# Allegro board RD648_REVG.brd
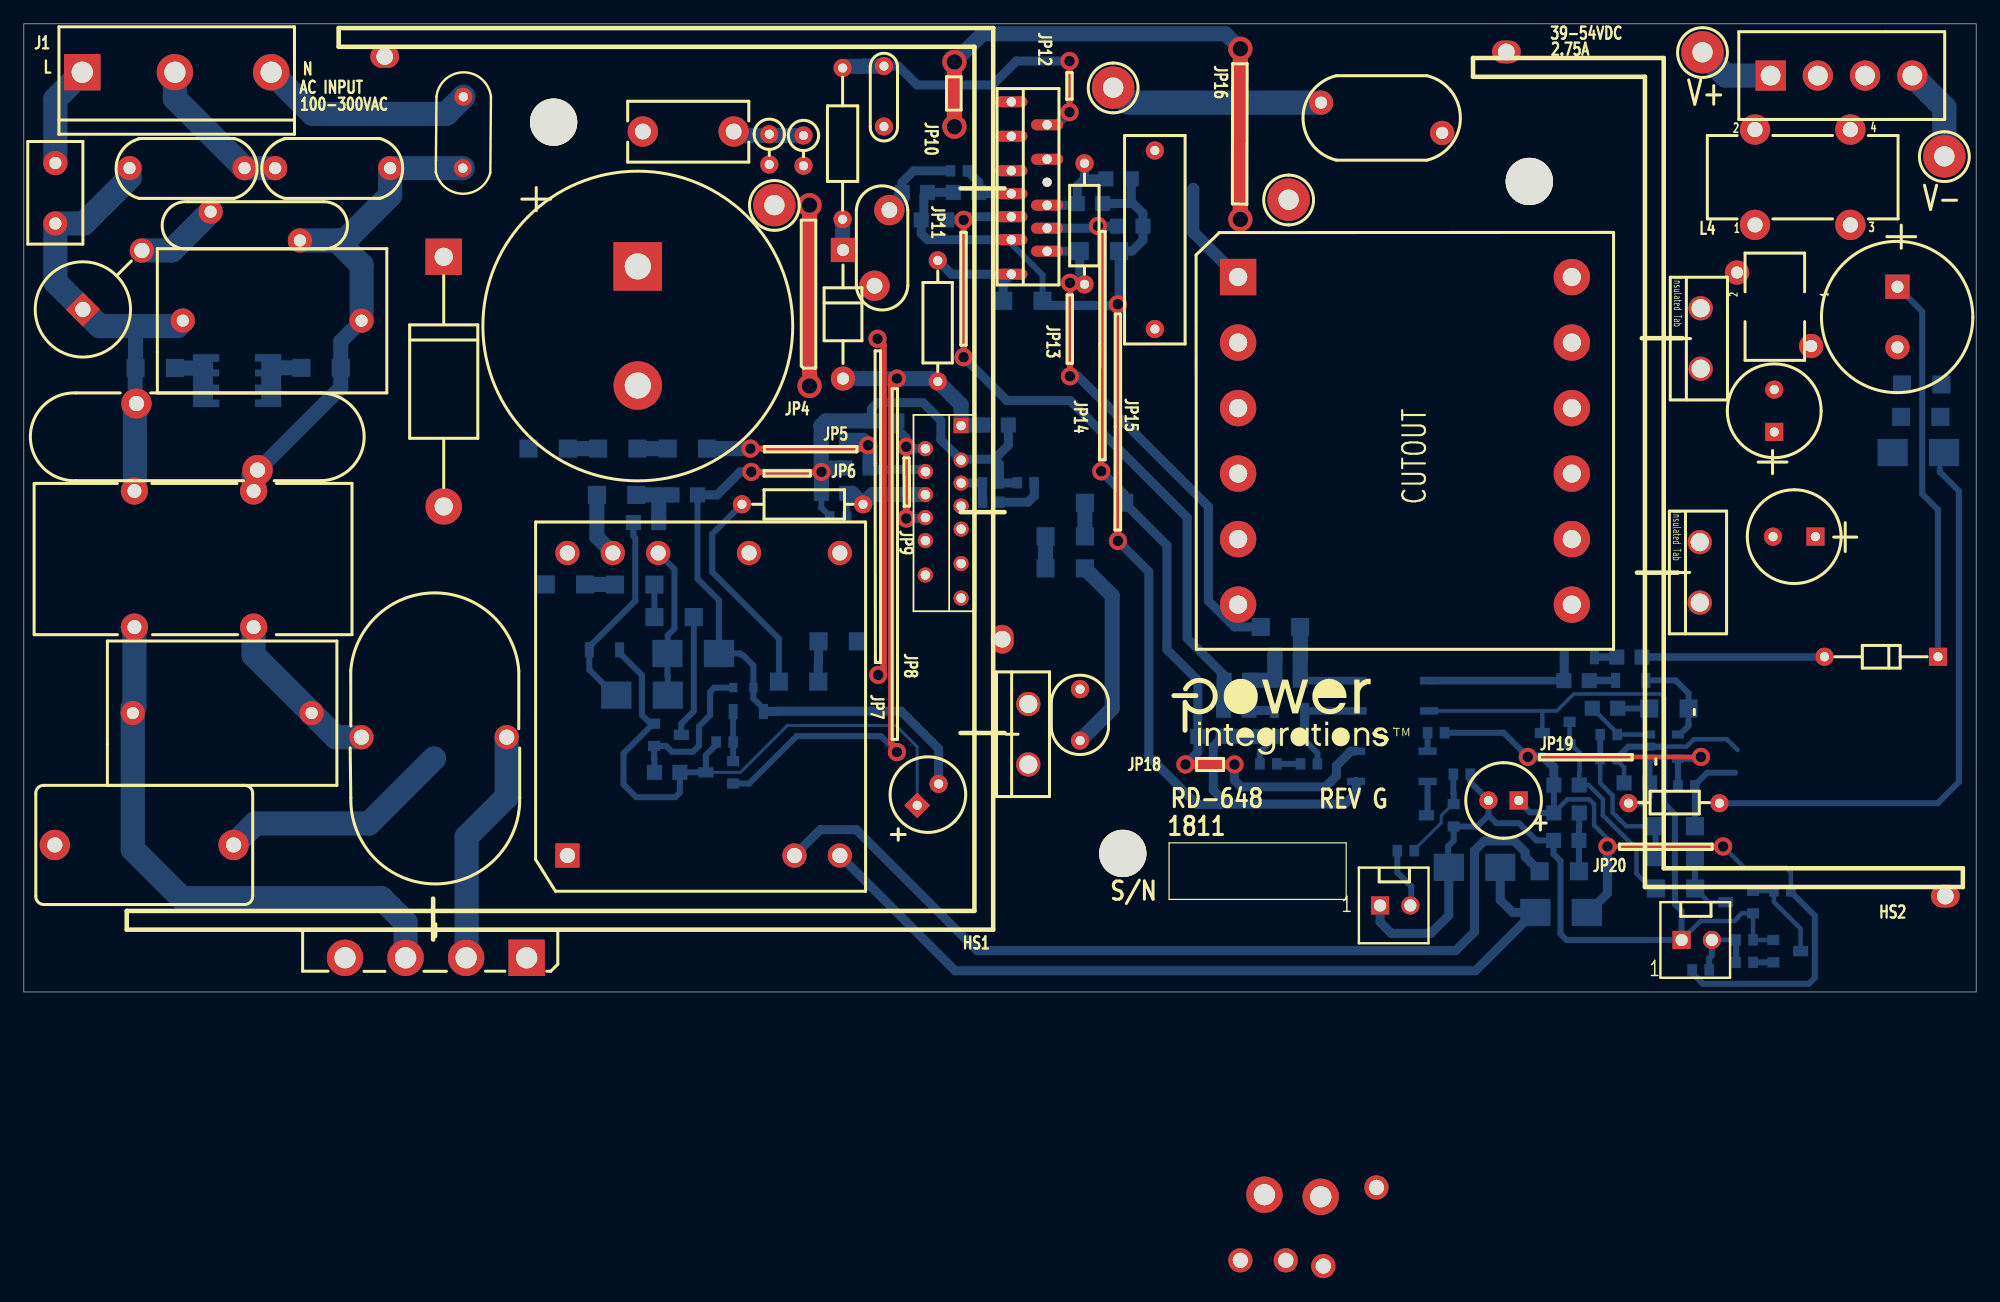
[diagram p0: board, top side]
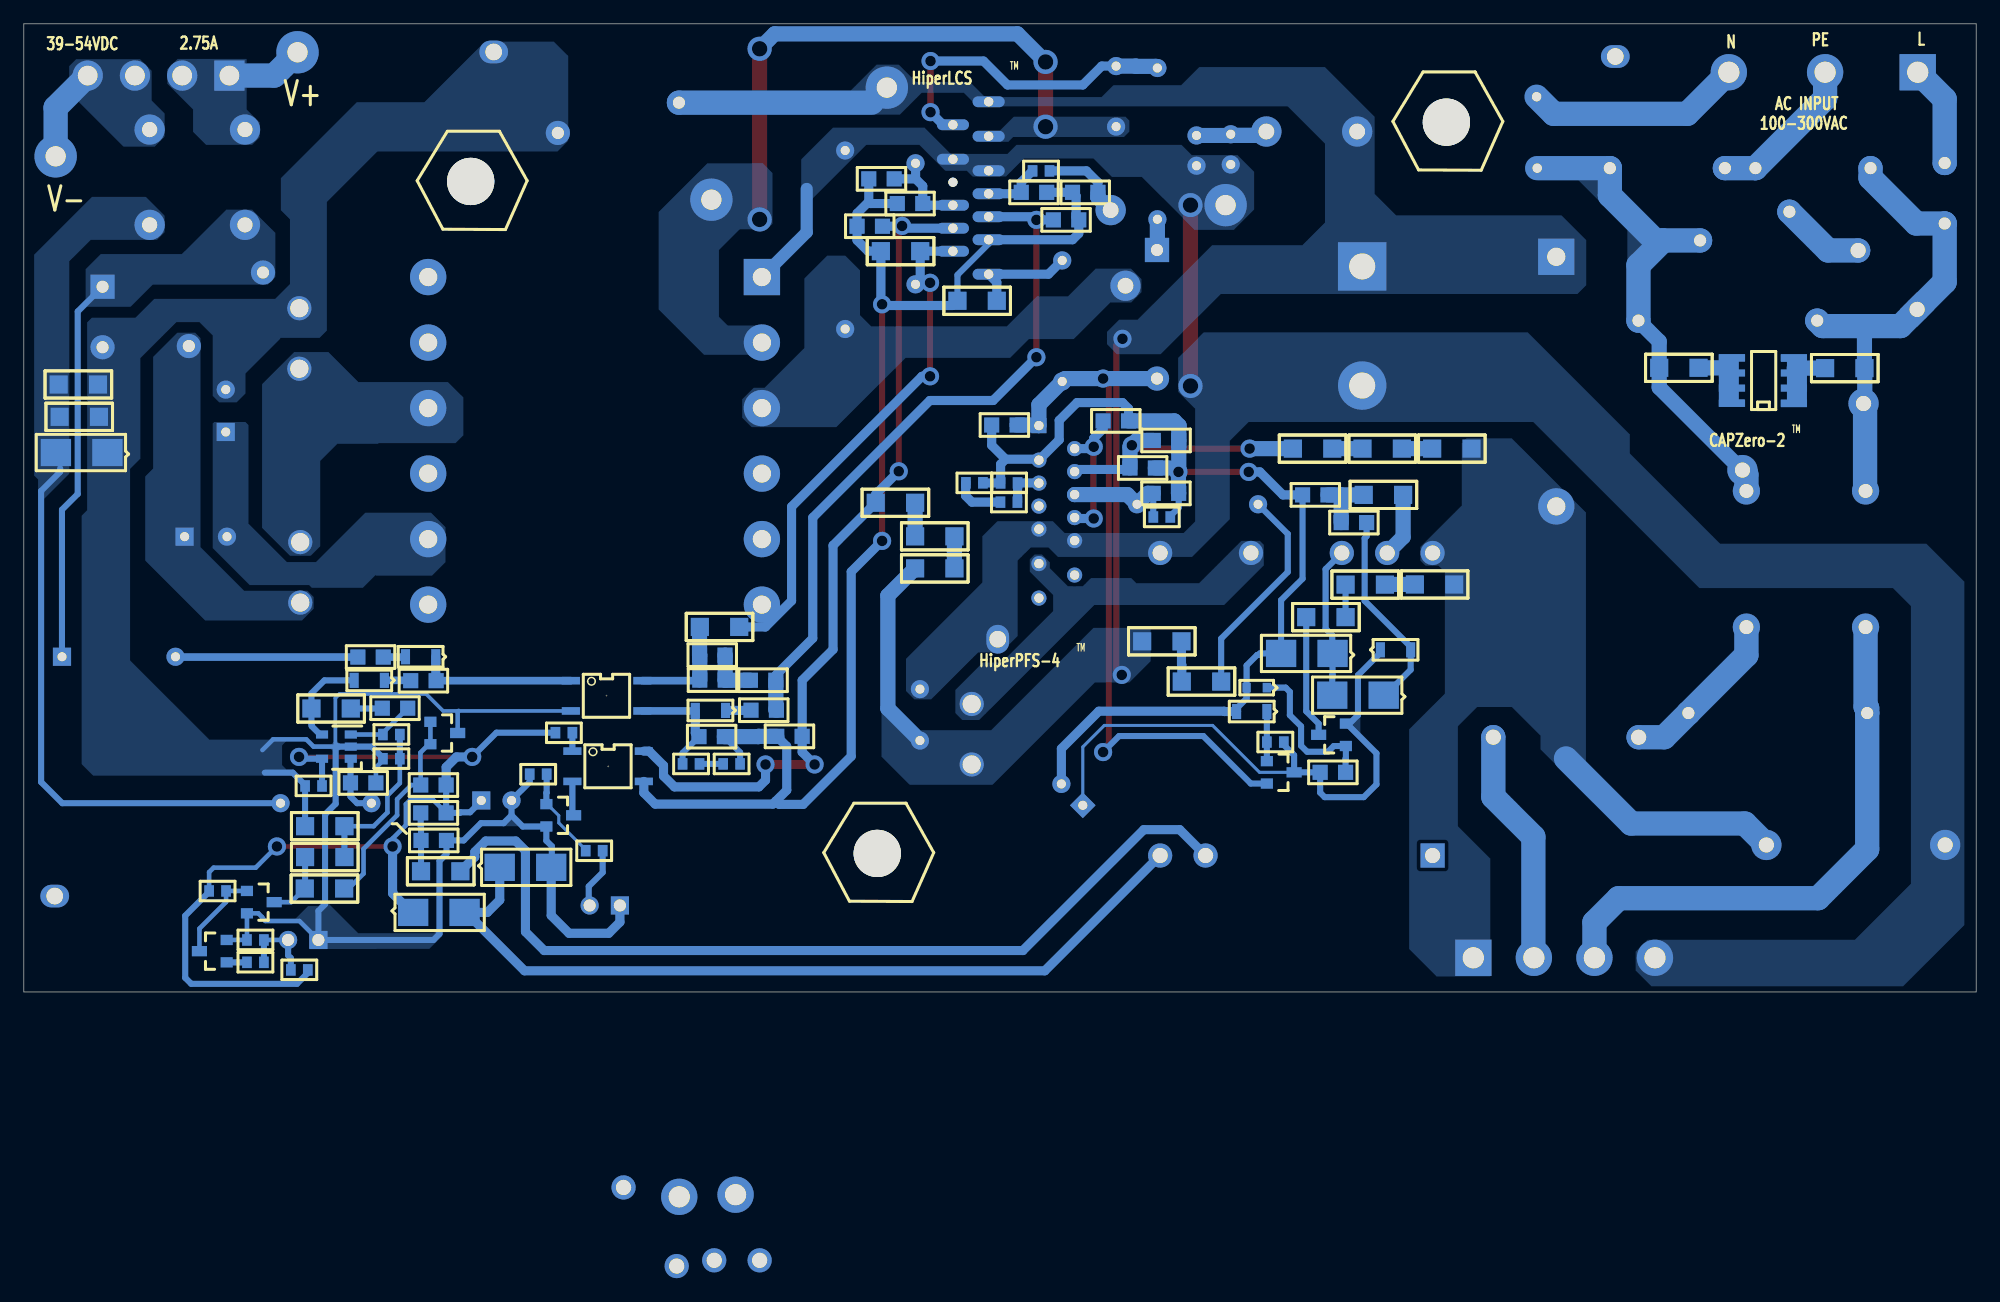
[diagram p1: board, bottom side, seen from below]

Outline 163.8 x 81.28 mm; copper layers: TOP, BOTTOM. Coordinates in mm from the lower left corner of the outline.
Outline path: 0,81.28 163.8,81.28 163.8,0 0,0 0,81.28

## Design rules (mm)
constraint set DEFAULT: min track width 0.508

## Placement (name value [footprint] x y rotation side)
BR1  GBU8J  [PIDAXBRIDGEGBU8]  42.19 2.87 180 top
C1  680 pF  [PINPYCAPRAD470X210LS380040]  8.86 69.16 0 top
C2  680 pF  [PINPYCAPRAD470X210LS380040]  21.08 69.16 0 top
C3  680 nF  [PINPXCAPRAD710X430720040]  13.34 56.36 0 top
C4  680 nF  [PINPXCAPRAD710X430720040]  9.14 23.42 0 top
C5  0.68 uF  [PI_NP_CAPRAD18P2X10LS15MMD050]  17.6 12.34 180 top
C6  100 nF  [PISMC0805]  51.14 39.41 0 bottom
C7  100 nF  [PISMC0805]  54.38 41.73 0 bottom
C8  100 nF  [PISMC0805]  128.37 15.04 0 bottom
C9  100 nF  [PISMC0805]  130.48 12.73 180 bottom
C10  220 uF  [PIPOLCAPCYLD250LS100030]  125.43 16.08 180 top
C11  100 uF  [PIPOLCAPCYLD250LS100030]  74.96 15.67 45 top
C12  3.3 uF  [PISMC0805]  80.47 47.6 0 bottom
C13  1 uF  [PISMC0805]  73.25 47.94 180 bottom
C14  470 pF  [PISMC0805]  71 43.99 180 bottom
C15  100 nF  [PISMC0603]  80.43 42.74 0 bottom
C16  1 uF  [PISMC0603]  84.76 42.75 180 bottom
C17  10 nF  [PI_NP_CAP250X200LS170D030]  88.62 21.11 90 top
C18  470 pF  [PISMC0805]  69.04 41.86 180 bottom
C19  100 uF  [PIPOLCAPCLYD25MMLS10MMD086]  51.51 60.91 270 top
C20  2.2 nF  [PINPYCAPRAD540X290LS400040]  108.84 74.66 0 top
C21  680 nF  [PISMC0805]  107.09 26.19 180 bottom
C22  22 nF  [PISMC0805]  91.76 64.29 0 bottom
C23  4.7 nF  [PISMC0805]  88.38 66.19 0 bottom
C24  1 uF  [PISMC1206]  88.6 62.19 0 bottom
C25  1 uF  [PISMC1206]  82.17 58.03 0 bottom
C26  4.7 nF  [PISMC0805]  77.43 64.82 180 bottom
C27  1 nF  [PISMC0805]  80.12 67.13 180 bottom
C28  47 nF  [PI_NP395X200LS300D040]  51.94 72.24 0 top
C29  12nF  [PI_NP_CAP689X200LS590D030]  94.89 70.65 270 top
C30  47 pF  [PINPCAPRAD370X156250040]  72.64 65.64 270 top
C31  330 nF  [PINPCAPRAD200X100200030]  72.16 77.73 270 top
C32  82 uF  [PIPOLCAPCLYD320LS140030]  150.32 38.23 180 top
C33  82 uF  [PIPOLCAPCLYD320LS140030]  146.86 47.02 90 top
C34  180 uF  [PIPOLCAPCLYD500LS200040]  157.2 59.21 270 top
C35  6.8 nF  [PISMC0805]  131.6 23.83 0 bottom
C36  100 nF  [PISMC0603]  138.79 17.3 0 bottom
C37  1 uF  [PISMC1206]  136.91 13.92 0 bottom
C38  3.3 nF  [PISMC0805]  136.4 17.55 180 bottom
C39  100 nF  [PISMC0603]  105.13 19.15 180 bottom
D1  BAV19WS  [PISMSOD323]  49.99 28.73 180 bottom
D2  ES1C-13-F  [PISMDO214AC12]  49.71 24.92 0 bottom
D3  ES1C-13-F  [PISMDO214AC12]  54 28.42 0 bottom
D4  1N5407-E3/54  [PIDV300X200X060DO15D0201AD]  35.23 61.72 270 top
D5  ES1C-13-F  [PISMDO214AC12]  131.14 6.68 180 bottom
D6  ES1C-13-F  [PISMDO214AC12]  123.88 10.46 180 bottom
D7  LXA03T600  [PIDVT0220ACREVA]  84.28 24.18 270 top
D8  BAV19WS  [PISMSOD323]  104.93 23.64 0 bottom
D9  UF4005  [PIDAX475X125040DO41]  68.73 62.29 270 top
D10  MBRF10H100-E3/45  [PIDVITO220FPAC]  140.61 37.77 270 top
D11  MBRF10H100-E3/45  [PIDVITO220FPAC]  140.69 57.4 270 top
D12  BAV19WS  [PISMSOD323]  129.24 28.14 0 bottom
D13  BAV19WS  [PISMSOD323]  133.55 26.16 0 bottom
D14  GS1A-LTP  [PISMDO214AC12]  156.79 45.29 0 bottom
F1  3.15 A  [PI_RST_MICROFUSE]  2.64 69.6 270 top
GDT1  GDT 500V  [PI_AXD8XL6MM050V]  4.95 57.3 45 top
HS1  HEATSINK,  FAB, DER648, PI CUST  [HS_2P_DER648A]  81.33 5.23 0 top
HS2  HEATSINK,  FAB, DER648, PI CUST  [HS_2P_DER648B]  136.02 8.81 270 top
J1  CON5  [PI_HDR_5PIN_LS156_LCK]  4.9 77.22 90 top
J2  CON2  [PI_MOLEX_2POL]  139.09 4.37 0 top
J3  CON4  [PI_HDR_4PIN]  146.56 76.93 270 top
J6  CON2  [PI_MOLEX_2POL]  113.79 7.26 0 top
JP1  0.0  [PISMR1206]  48.08 41.73 0 bottom
JP2  0.0  [PISMR1206]  127.18 10.13 0 bottom
JP3  0.0  [PISMR1206]  103.78 30.65 0 bottom
L1  9 mH  [PI_IND_4P_500X1050LS450D46]  19.28 42.06 270 top
L2  330 uH  [PI_TOROID_2P_550X950_LS480_D050]  28.32 21.39 0 top
L3  300 nH  [PI_OUT_DER648]  146.91 57.53 90 top
L4  120 uH  [PI_TOROID_DER648CMC]  149.25 68.4 0 top
NOREF  -  []  -0.03 81.28 0 top
NOREF#2  -  []  -228.45 -139.73 0 top
NOREF#3  -  []  96.29 26.34 0 top
NOREF#4  -  []  0 0 90 top
NOREF#5  -  []  -95.48 52.65 0 top
POST-CRKT_BRD_6-32_HEX1  Post Hex, 6-32, snap, 0.50"L, NYL  [PIMTGHOLED156]  44.45 73.03 180 bottom
POST-CRKT_BRD_6-32_HEX2  Post Hex, 6-32, snap, 0.50"L, NYL  [PIMTGHOLED156]  92.2 11.63 180 bottom
POST-CRKT_BRD_6-32_HEX3  Post Hex, 6-32, snap, 0.50"L, NYL  [PIMTGHOLED156]  126.31 68.05 180 bottom
Q1  BSS126H6327XTSA2  [PISMSOT23123_1]  52.88 22.53 90 bottom
Q2  MMBT4401LT1G  [PISMSOT23123_1]  59.51 17.5 270 bottom
Q3  2N7002  [PISMSOT23123_1]  145.08 6.6 270 bottom
Q4  MMBT4401LT1G  [PISMSOT23123_1]  146.79 4.37 90 bottom
Q5  MMBT4401LT1G  [PISMSOT23123_1]  119.96 13.89 270 bottom
R1  150 k  [PISMR1206]  9.37 52.37 0 bottom
R2  150 k  [PISMR1206]  23.29 52.4 0 bottom
R3  7.5 k  [PISMR1206]  43.79 34.21 0 bottom
R4  7.5 k  [PISMR1206]  49.61 34.2 0 bottom
R5  7.5 k  [PISMR1206]  52.91 31.47 0 bottom
R6  1.3 M  [PISMR0805]  52.91 18.44 0 bottom
R7  6.2 M  [PISMR1206]  45.64 45.62 180 bottom
R8  6.2 M  [PISMR1206]  48.18 45.62 0 bottom
R9  3.74 M  [PISMR1206]  54.03 45.62 0 bottom
R10  2.2 k  [PISMR0603]  58.09 20.98 0 bottom
R11  143 k  [PISMR0805]  69.04 46.3 180 bottom
R12  30.1 k  [PISMR0603]  80.44 41.12 0 bottom
R13  3.74 M  [PISMR1206]  69.98 29.44 180 bottom
R14  6.2 M  [PISMR1206]  66.65 26.06 180 bottom
R15  6.2 M  [PI14WRESD100LS500D030]  70.41 40.94 180 top
R16  143 k  [PISMR0603]  67.61 39.88 0 bottom
R17  1.20 M  [PISMR1206]  85.72 35.56 0 bottom
R18  1.20 M  [PISMR1206]  85.72 38.25 0 bottom
R19  1.20 M  [PISMR1206]  89.03 41.07 0 bottom
R20  21.0 k  [PISMR0805]  98.5 21.46 0 bottom
R21  4.7 k  [PISMR0805]  107.16 21.44 180 bottom
R22  127 k  [PISMR0805]  90.78 68.27 0 bottom
R23  90.9 k  [PISMR0805]  107.11 28.28 180 bottom
R24  1 k  [PISMR0805]  102.79 23.66 180 bottom
R25  5.76 k  [PISMR0805]  102.84 26.17 180 bottom
R26  2.2  [PI14WRESD100LS400D030#2]  68.7 64.87 90 top
R27  4.7  [PI14WRESD100LS500D030]  76.68 51.26 90 top
R28  6.81 k  [PI14WRESD100LS400D030]  88.99 59.41 90 top
R29  1  [PI14WVRESD100LS100D030]  65.42 71.91 270 top
R30  1  [PI14WVRESD100LS100D030]  62.54 72.01 270 top
R31  220  [PISMR0603]  79.17 68.94 180 bottom
R32  43  [PISMR0805]  75.82 67.13 180 bottom
R33  33 k  [PISMR0805]  135.78 28.12 180 bottom
R34  1 k  [PISMR0805]  129.21 26.14 0 bottom
R35  10 k  [PISMR1206]  139.67 23.8 180 bottom
R36  2.2 k  [PISMR0805]  128.37 17.37 0 bottom
R37  10 k  [PISMR0603]  132.26 21.62 0 bottom
R38  16.2 k  [PISMR1206]  140.23 8.69 180 bottom
R39  9.09 k  [PISMR0603]  132.26 19.58 0 bottom
R40  10 k  [PI18WVRESD80LS100D030]  142.27 15.85 180 top
R41  0.05  [PISMR1206]  160.88 51 180 bottom
R42  0.05  [PISMR1206]  160.81 48.29 180 bottom
R43  22 k  [PISMR0603]  139.98 1.85 0 bottom
R44  39 k  [PISMR0603]  143.66 4.37 0 bottom
R45  22 k  [PISMR0603]  148.26 8.48 180 bottom
R46  39 k  [PISMR0603]  143.66 2.49 0 bottom
R48  301 k  [PISMR1206]  140.21 11.33 180 bottom
R49  10 k  [PISMR0603]  116.66 11.86 180 bottom
R50  22 k  [PISMR0603]  121.36 18.29 180 bottom
R51  22 k  [PISMR0603]  119.2 21.77 180 bottom
R52  2.2 k  [PISMR0603]  108.53 19.15 180 bottom
RT1  2.5  [PI_RAD180X395LS235D031]  36.88 75.16 269.5 top
RV1  470 VAC  [PI_DISC1100X290LS400X220D050]  9.45 49.4 0 top
RV2  470 VAC  [PIDISC610X212LS295X95040]  15.67 65.51 0 top
T1  489 uH  [PI_PFC_DER648]  45.61 11.46 90 top
T2  490 uH  [PI_BOBBIN_ETD34_12P_CUTOUT]  101.85 60.05 0 top
TP1  CON1  [PITPKEYSTONE125X125]  91.4 75.92 0 top
TP2  CON1  [PITPKEYSTONE125X125]  62.97 66.06 0 top
TP3  CON1  [PITPKEYSTONE125X125]  106.12 66.51 0 top
TP4  CON1  [PITPKEYSTONE125X125]  140.84 78.89 0 top
TP5  CON1  [PITPKEYSTONE125X125]  161.14 70.15 0 top
U1  CAP200DG  [PI_IC_SMD_SO8_CAPZERO]  15.29 49.43 90 bottom
U2  PFS7625H  [PI_IC_ESIP16-13_SLOT_HPII]  78.64 47.55 270 top
U3  PC357A  [PI_4_SMD]  114.91 24.87 270 bottom
U4  LCS702HG  [PI_IC_ESIP16-13_OVAL_SLOT]  82.85 60.26 90 top
U5  LM321  [PISMSOT235]  136.37 19.58 90 bottom
U6  LM431AIM3  [PISMSOT23123]  129.69 20.8 270 bottom
U7  PC357A  [PI_4_SMD]  114.78 18.95 270 bottom
VR1  DZ2S091M0L  [PI_SM_D_SSMINI2P]  59.51 25.55 0 bottom
VR2  BZX384-B13,115  [PISMSOD323]  59.51 23.55 0 bottom
VR3  1N5259B-T  [PIDAX375X070030DO35]  160.6 28.14 180 top

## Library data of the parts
BR1 = DISCRETE BRIDGE_+~~-: room: 2
C1 C2 C17 = CAP NP: tolerance: 20; room: 2
C3 C4 = CAP NP: alternate symbols: (pinpxcaprad710x430720040_h); room: 2
C5 = CAP NP: alternate symbols: (pi_np_caprad18p2x10ls15mmd050)
C6-C9 = CAP NP
C10 = CAP POL
C11 = CAP POL: alternate symbols: (pipolcapclyd250ls100d30h590)
C12-C16 C18 = CAP NP: room: 2
C19 = CAP POL: room: 2
C20 = CAP NP: alternate symbols: (pinpycaprad540x290ls400040h); room: 3
C21 C22 C24 C25 C28 C29 C31 = CAP NP: room: 3
C23 C26 C27 = CAP NP: tolerance: 10; room: 3
C30 = CAP NP: tolerance: 5; room: 3
C32 C33 = CAP POL: alternate symbols: (pipolcapclyd320ls140d30h470); room: 4
C34 = CAP POL: alternate symbols: (pipolcapclyd500ls200040690lh); room: 4
C35-C39 = CAP NP: room: 4
D1 = DIODE: room: 2
D2 D3 D5 D6 = DIODE
D4 = DIODE: alternate symbols: (pidax800x225060do15do201ad,pidv300x200x060do14wbead,pidv600x200x060do14); room: 2
D7 = DIODE: alternate symbols: (PI_TO220); room: 2
D8 = DIODE: room: 3
D9 = DIODE: alternate symbols: (pidax475x125040do41,pidax390x125040do41); room: 3
D10 D11 = DIODE SCHOTTKY: room: 4
D12-D14 = DIODE: room: 4
F1 = FUSE: alternate symbols: (pirstmicrofusehoz); room: 2
GDT1 = GDT
HS1 = hs_2P_DER648a
HS2 = hs_2P_DER648b
J1 = CON5
J2 J6 = CON2
J3 = CON4: room: 4
JP1 JP2 = JUMPER_1
JP3 = JUMPER_1: room: 3
L1 = INDUCTOR_4P_revB
L2 = INDUCTOR: room: 2
L3 = INDUCTOR
L4 = TORRID 4P_12_34
POST-CRKT_BRD_6-32_HEX1-POST-CRKT_BRD_6-32_HEX3 = POST_CRKT_BRD_6-32_HEX
Q1 Q3 = FET_N_GSD
Q2 = NPN_BEC: room: 2
Q4 Q5 = NPN_BEC
R1-R14 R16 = R: room: 2
R15 = R: alternate symbols: (pi14wvresd100ls200d030,pi14wresd100ls400d030,pi14wresd100ls500d030); room: 2
R17 R20 R37 R38 R43-R46 R48-R52 = R
R18 R19 = R: tolerance: 1%
R21 = R: tolerance: 5%
R22-R25 R31 R32 = R: room: 3
R26-R30 = R: alternate symbols: (pi14wvresd100ls200d030,pi14wresd100ls400d030,pi14wresd100ls500d030); room: 3
R33-R36 R39 R41 R42 = R: room: 4
R40 = R: alternate symbols: (pi18wresd080ls300d030); room: 4
RT1 = THERMISTOR: alternate symbols: (pirad550x410ls300040_h); room: 2
RV1 RV2 = VARISTOR
T1 = PFC_7p_DER648_0
T2 = pi_llcxfrmr_DER648_0
TP1-TP3 = TESTPOINT: room: 3
TP4 TP5 = TESTPOINT: room: 4
U1 = CAPZero: room: 2
U2 = HIPERPFS-4-eSIP-16G: alternate symbols: (pi_ic_esip16-13_socket_hpii,pi_ic_esip16-13_oval_hpii,pi_ic_eesip_socket); room: 2
U3 U7 = OPTO_A_B
U4 = LC_SWITCH_Rev03: room: 3
U5 = LM321_SOT23-5: room: 4
U6 = TL431/SOT-23_CAR: room: 4
VR1 VR2 = DIODE_ZENER: room: 2
VR3 = DIODE_ZENER: alternate symbols: (pidax375x070030do35); room: 4

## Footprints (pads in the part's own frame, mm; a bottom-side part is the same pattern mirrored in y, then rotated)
HS_2P_DER648A
  oval 2.413x1.905 hole 1.397: 1(-51.054,73.304)
  oval 1.905x2.413 hole 1.397: 2(0.762,24.384)
HS_2P_DER648B
  oval 1.905x2.413 hole 1.397: 1(-70.104,-11.633) 2(0.762,25.197)
PI14WRESD100LS400D030
  round 1.524 hole 0.762: 1(0,0) 2(10.16,0)
PI14WRESD100LS400D030#2
  round 1.524 hole 0.762: 1(0,0) 2(12.7,0)
PI14WRESD100LS500D030
  round 1.524 hole 0.762: 1(0,0) 2(10.16,0)
PI14WVRESD100LS100D030
  round 1.524 hole 0.762: 1(0,0) 2(2.54,0)
PI18WVRESD80LS100D030
  round 1.524 hole 0.762: 1(0,0) 2(7.62,0)
PI_4_SMD
  rect 0.635x1.524 smd: 1(-1.27,-2.997) 2(1.27,-2.997) 3(1.27,2.997) 4(-1.27,2.997)
PI_AXD8XL6MM050V
  rect 2.032x2.032 hole 1.27: 1(0,0)
  round 2.032 hole 1.27: 2(7,0)
PI_BOBBIN_ETD34_12P_CUTOUT
  rect 3.048x3.048 hole 1.524: 1(0.025,-0.025)
  round 3.048 hole 1.524: 2(0.025,-5.524) 3(0.025,-11.026) 4(0.025,-16.525) 5(0.025,-22.024) 6(0.025,-27.526) 7(28.026,-27.526) 8(28.026,-22.024) 9(28.026,-16.525) 10(28.026,-11.026) 11(28.026,-5.524) 12(28.026,-0.025)
PI_DISC1100X290LS400X220D050
  round 2.54 hole 1.27: 1(0,0) 2(10.16,-5.588)
PI_HDR_4PIN
  rect 2.54x2.54 hole 1.651: 1(0,0)
  round 2.54 hole 1.651: 2(0,3.962) 3(0,7.925) 4(0,11.887)
PI_HDR_5PIN_LS156_LCK
  rect 3.048x3.048 hole 1.778: 1(0,0)
  round 3.048 hole 1.778: 2(-94.234,-99.187) 3(0,-7.772) 4(-94.412,-103.911) 5(0,-15.85)
PI_IC_ESIP16-13_OVAL_SLOT
  oval 0.914x2.692 hole 0.787: 1(0,0) 3(1.93,-2.997) 4(2.896,0) 5(3.861,-2.997) 6(4.826,0) 7(5.791,-2.997) 8(6.756,0) 10(8.687,0) 11(9.652,-2.997) 13(11.582,0) 14(12.548,-2.997) 16(14.478,0)
  round 0.762 hole 0.762: 9(7.722,-2.997)
PI_IC_ESIP16-13_SLOT_HPII
  rect 1.27x1.27 hole 0.787: 1(0,0)
  round 1.27 hole 0.787: 3(1.93,-2.997) 4(2.896,0) 5(3.861,-2.997) 6(4.826,0) 7(5.791,-2.997) 8(6.756,0) 9(7.722,-2.997) 10(8.687,0) 11(9.652,-2.997) 13(11.582,0) 14(12.548,-2.997) 16(14.478,0)
PI_IC_SMD_SO8_CAPZERO
  rect 0.599x2.2 smd: 1(0,0) 2(1.27,0) 3(2.54,0) 4(3.81,0) 5(3.81,5.199) 6(2.54,5.199) 7(1.27,5.199) 8(0,5.199)
PI_IND_4P_500X1050LS450D46
  round 2.286 hole 1.168: 1(0,0) 2(11.43,0) 3(0,-10) 4(11.43,-10)
PI_MOLEX_2POL
  rect 1.524x1.524 hole 1.016: 1(0,0)
  round 1.524 hole 1.016: 2(2.54,0)
PI_NP395X200LS300D040
  round 2.54 hole 1.321: 1(0,0) 2(7.62,0)
PI_NP_CAP250X200LS170D030
  round 1.524 hole 0.762: 1(0,0) 2(4.318,0)
PI_NP_CAP689X200LS590D030
  round 1.524 hole 0.762: 1(0,0) 2(14.986,0)
PI_NP_CAPRAD18P2X10LS15MMD050
  round 2.54 hole 1.27: 1(0,0) 2(15.001,0)
PI_OUT_DER648
  round 2.032 hole 1.016: 1(-3.302,-3.048) 2(2.87,3.175)
PI_PFC_DER648
  rect 2.032x2.032 hole 1.27: 1(0,0)
  round 2.032 hole 1.27: 2(-33.985,-56.464) 3(-33.985,-60.274) 4(-34.468,-63.424) 5(0,-19.05) 6(0,-22.86) 7(25.4,-22.86) 8(-27.866,-67.882) 9(25.4,-15.24) 10(25.4,-7.62) 11(25.4,-3.81) 12(25.4,0)
PI_RAD180X395LS235D031
  round 1.524 hole 0.787: 1(0,0) 2(5.994,0)
PI_RST_MICROFUSE
  round 2.032 hole 1.016: 1(0,0) 2(5.08,0)
PI_SM_D_SSMINI2P
  rect 0.699x0.8 smd: 1(0,0) 2(1.699,0)
PI_TOROID_2P_550X950_LS480_D050
  round 2.032 hole 1.27: 1(0,0) 2(12.192,0)
PI_TOROID_DER648CMC
  round 2.54 hole 1.27: 1(-4,-4) 2(-4,4) 3(4,-4) 4(4,4)
PIDAX375X070030DO35
  rect 1.524x1.524 hole 0.762: 1(0,0)
  round 1.524 hole 0.762: 2(9.525,0)
PIDAX475X125040DO41
  rect 2.032x2.032 hole 1.016: 1(0,0)
  round 2.032 hole 1.016: 2(10.795,0)
PIDAXBRIDGEGBU8
  rect 3.048x3.048 hole 1.778: 1(0,0)
  round 3.048 hole 1.778: 2(5.08,0) 3(10.16,0) 4(15.24,0)
PIDISC610X212LS295X95040
  round 2.032 hole 1.016: 1(0,0) 2(7.493,-2.413)
PIDV300X200X060DO15D0201AD
  rect 3.048x3.048 hole 1.524: 1(0,0)
  round 3.048 hole 1.524: 2(20.955,0)
PIDVITO220FPAC
  round 2.032 hole 1.524: 1(5.08,0) 2(0,0)
PIDVT0220ACREVA
  round 2.032 hole 1.524: 1(5.08,0) 2(0,0)
PIMTGHOLED156
  round 3.962 hole 3.962: 1(0,0)
PINPCAPRAD200X100200030
  round 1.524 hole 0.762: 1(0,0) 2(5.08,0)
PINPCAPRAD370X156250040
  round 2.54 hole 1.321: 1(0,-0.025) 2(6.35,-1.27)
PINPXCAPRAD710X430720040
  round 2.032 hole 1.016: 1(0,0) 2(15.001,0)
PINPYCAPRAD470X210LS380040
  round 2.032 hole 1.016: 1(0,0) 2(9.652,0)
PINPYCAPRAD540X290LS400040
  round 2.032 hole 1.016: 1(0,0) 2(10.16,-2.54)
PIPOLCAPCLYD25MMLS10MMD086
  rect 4.064x4.064 hole 2.184: 1(0,0)
  round 4.064 hole 2.184: 2(10,0)
PIPOLCAPCLYD320LS140030
  rect 1.524x1.524 hole 0.762: 1(0,0)
  round 1.524 hole 0.762: 2(3.556,0)
PIPOLCAPCLYD500LS200040
  rect 2.032x2.032 hole 1.016: 1(0,0)
  round 2.032 hole 1.016: 2(5.08,0)
PIPOLCAPCYLD250LS100030
  rect 1.524x1.524 hole 0.762: 1(0,0)
  round 1.524 hole 0.762: 2(2.54,0)
PISMC0603
  rect 0.813x0.965 smd: 1(0,0) 2(1.422,0)
PISMC0805
  rect 1.27x1.27 smd: 1(0,0) 2(2.134,0)
PISMC1206
  rect 1.524x1.524 smd: 1(0,0) 2(3.302,0)
PISMDO214AC12
  rect 2.54x2.286 smd: 1(0,0) 2(4.318,0)
PISMR0603
  rect 0.813x0.965 smd: 1(0,0) 2(1.422,0)
PISMR0805
  rect 1.27x1.27 smd: 1(0,0) 2(2.134,0)
PISMR1206
  rect 1.524x1.524 smd: 1(0,0) 2(3.302,0)
PISMSOD323
  rect 0.762x1.27 smd: 1(0,0) 2(2.54,0)
PISMSOT235
  rect 0.686x1.016 smd: 1(0,0) 2(1.016,0) 3(2.032,0) 4(2.032,2.413) 5(0,2.413)
PISMSOT23123
  rect 0.864x1.016 smd: 1(-1.88,0) 3(0,0)
  rect 0.864x1.27 smd: 2(-0.94,2.286)
PISMSOT23123_1
  rect 0.864x1.016 smd: 1(-1.88,0) 2(0,0)
  rect 0.864x1.27 smd: 3(-0.94,2.286)
PITPKEYSTONE125X125
  round 3.556 hole 1.702: 1(0,0)

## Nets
GND_EARTH: C1.2 C2.1 J1.3
VCCP: C6.1 D1.2 D2.1
VCCPR: C12.1 D9.2 Q2.2(EMITTER) R27.1 U2.1(VCC)
VCCS: C8.1 C10.1 C36.1 D5.1 R36.1 R43.1 R45.1 R51.1 U5.5
B+: C17.1 C19.1 C20.1 C28.1 D4.1 D7.1 R13.1 R17.2 TP1.1 U4.16
G: C7.2 C11.2 C12.2 C13.2 C14.2 C15.2 C16.2 C18.2 D3.2 R11.2 R16.1 U2.4 VR1.2 VR2.2
K: U2.16
RTN: BR1.4 C5.2 C17.2 C19.2 C29.1 HS1.2 R29.2 R30.2 T1.7 T2.1 TP2.1 U2.10 U2.11 U4.10 U4.11
SRTN: C9.2 C10.2 C20.2 C33.2 C34.2 C36.2 C37.2 C38.2 D6.2 D11.2 D14.1 HS2.1 J2.1 J6.1 Q3.2(S) Q4.2(EMITTER) Q5.2(EMITTER) R39.2 R41.2 R42.2 R44.2 R50.1 U3.2 U5.2(V-) U6.2
VRECT: BR1.1 C5.1 D4.2 R3.1 R7.2 T1.12
N11361629: BR1.3(AC2) C4.1 L1.4
N11361637: BR1.2 L2.2
N11361645: F1.1 J1.1
N11361649: C1.1 C3.1 F1.2 GDT1.1 L1.3 R1.1 RV1.1
N11361735: J1.5 RT1.1
N11361765: R1.2 U1.1 U1.2 U1.3 U1.4
N11361893: R2.1 U1.5 U1.6 U1.7 U1.8(NC8)
N11361909: C2.2 C3.2 L1.1 R2.2 RT1.2 RV1.2 RV2.2
N11361917: C4.2 L1.2 L2.1
N11368602: R3.2 R4.1
N11368632: D7.2 T1.9 U2.13
N11368730: R13.2 R14.1
N11368734: R4.2 R5.1
N11368746: C18.1 R15.1 R16.2 U2.7
N11368794: C15.1 R12.1 U2.6
N11368862: Q1.3 R5.2
N11368870: R7.1 R8.1
N11368874: R8.2 R9.1
N11368882: C14.1 R9.2 R11.1 U2.5
N11368906: R14.2 R15.2
N11368928: C11.1 D1.1 Q1.2(S) Q2.3 R6.2 R10.1
N11368966: Q1.1 R6.1 VR1.1
N11368994: C13.1 U2.3 U2.9
N11369180: C16.1 R12.2
N11369212: Q2.1 R10.2 VR2.1
N11375827: D9.1 R26.1
N11375939: R17.1 R18.1
N11375959: C31.1 R26.2 U4.14
N11375963: C28.2 R29.1 R30.1
N11375997: C25.1 R27.2 U4.1
N11376097: C31.2 T2.2 TP3.1 U4.13
N11376117: C22.1 R19.2 R20.1 U4.5 U7.4
N11376317: C21.1 JP3.2 R23.1 U3.4
N11376341: C24.1 JP3.1 R28.1 U4.3(VREF)
N11376649: C21.2 R23.2 R25.1
N11376707: C23.1 R22.1 R28.2 U4.7
N11376799: D8.2 R21.1 R52.1 U3.3(E)
N11376923: C26.1 R24.2 R25.2 U4.6
N11377121: C22.2 C23.2 C24.2 C25.2 C26.2 C27.2 C39.2 R20.2 R21.2 R22.2 R32.1 U4.4 U7.3(E)
N11377143: C27.1 R31.1 U4.8
N11377647: C30.1 R31.2 R32.2
N11387015: C6.2 C7.1 JP1.2
N11387049: D2.2 D3.1 T1.10
N11394983: C29.2 C30.2 T2.3
N11395044: D10.2 D11.1 T2.10
N11395340: C32.1 D10.1 L3.1
N11396434: D5.2 D6.1 T1.6
N11396456: C8.2 C9.1 JP2.2
N11396474: JP2.1 T1.5
N11404287: C34.1 L3.2 L4.1 VR3.1
N11405404: D14.2 L4.3 R40.1 R41.1 R42.1
N11406552: D12.1 R34.1 U3.1
N11407305: D13.2 R35.1 U5.4
N11407588: R36.2 R38.2 U6.1 U6.3(VREF)
N11410539: C38.1 R40.2 U5.1
N11410712: C35.1 R37.2 U5.3
N11441238: Q3.1 Q4.3 R45.2
N11449111: JP1.1 T1.11
N11457086: D12.2 R33.2
N11457090: R33.1 VR3.2
N11461450: D13.1 R34.2
N11464509: C37.1 R37.1 R39.1 R48.2
N11469796: Q3.3 R38.1 R48.1
N11480149: C35.2 R35.2
N11512058: J3.1 J3.2 L4.2 TP4.1
N11512267: J3.3 J3.4 L4.4 TP5.1
N11532854: J2.2 R43.2 R44.1 R46.1
N11552445: Q4.1 R46.2
N11579928: Q5.3 U7.2
N11579932: Q5.1 R49.1 R50.2
N11579936: J6.2 R49.2
N11634216: C32.2 C33.1 T2.8
N11634313: C39.1 R52.2
N11640064: GDT1.2 RV2.1
N11642887: R51.2 U7.1
N113759751: R18.2 R19.1
N113768551: D8.1 R24.1

Pads without a net: HS1 1; HS2 2; J1 2 4; POST-CRKT_BRD_6-32_HEX1 1; POST-CRKT_BRD_6-32_HEX2 1; POST-CRKT_BRD_6-32_HEX3 1; T1 1 2 3 4 8; T2 4 5 6 7 9 11 12; U2 8 14; U4 9

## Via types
v1: diameter 2.032, hole 1.295, TOP to BOTTOM, 6 vias
v2: diameter 1.524, hole 0.889, TOP to BOTTOM, 26 vias

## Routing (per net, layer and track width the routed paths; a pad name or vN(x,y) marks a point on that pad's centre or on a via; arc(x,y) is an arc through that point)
GND_EARTH: length 13
  BOTTOM w2.032: C2.1 C1.2 12.67,75.01 J1.3
VCCP: length 17.2
  BOTTOM w0.508: D2.1 49.58,24.92 47.45,27.05 D1.2 47.45,28.98 51.31,32.84 51.31,38.1 51.14,38.27 C6.1
VCCPR: length 62.1
  TOP w0.508: v2(73.25,20.14) 73.25,20.37 72.77,20.85 72.77,51.02 v2(73.25,51.5)
  BOTTOM w0.508: v2(73.25,20.14) 71.91,21.49 64.85,21.49 60.86,17.5 Q2.2
  BOTTOM w1.27: D9.2 v2(73.25,51.5) 76.44,51.5 R27.1 78.64,49.3 U2.1 78.69,47.6 C12.1
VCCS: length 87.9
  TOP w0.381: v2(140.72,19.74) v2(126.19,19.74) ; v2(142.57,12.22) v2(132.87,12.22)
  BOTTOM w0.381: v2(132.87,12.22) 132.87,12.88 131.75,14 131.75,15.76 131.35,16.17 129.5,16.17 C8.1 ; R45.1 148.26,10.06 147.88,10.44 144.35,10.44 v2(142.57,12.22)
  BOTTOM w0.508: R51.1 124.16,21.77 v2(126.19,19.74) ; C36.1 U5.5 140.56,19.58 v2(140.72,19.74) ; R45.1 148.26,8.41 150.27,6.4 150.27,1.19 149.76,0.69 140.89,0.69 139.98,1.6 R43.1 ; 125.43,16.1 C10.1 125.43,16.03 126.36,15.09 127.18,15.09 127.23,15.04 C8.1 R36.1
  BOTTOM w0.762: R36.1 128.37,18.87 127.51,19.74 v2(126.19,19.74) ; v2(132.87,12.22) 132.87,8.43 132.86,8.43 132.86,8.27 131.27,6.68 D5.1
B+: length 61.3
  TOP w0.508: v2(71.69,26.62) 72.14,27.07 72.14,54.33 v2(71.63,54.84)
  BOTTOM w1.27: R17.2 91.31,33.27 91.31,23.8 C17.1
  BOTTOM w2.032: C20.1 92.66,74.66
G: length 89.3
  TOP w0.508: v2(66.93,43.66) v2(61.04,43.66)
  BOTTOM w0.508: C7.2 56.52,34.7 58.32,32.89 D3.2 60.1,28.42 60.22,28.3 60.33,28.3 61.21,27.41 VR1.2 61.21,24.64 62.05,23.8 VR2.2 ; 67.72,43.99 66.91,43.18 C18.2 66.91,40.66 67.61,39.95 R16.1
  BOTTOM w0.762: C16.2 83.32,42.74 C15.2 81.85,44.31 81.43,44.73 ; 81.43,44.73 82.6,45.9 C12.2 ; 81.43,44.73 78.71,44.73 U2.4 76.94,46.35 76.94,47.98 75.44,49.48 71.63,49.48 71.12,48.97 C13.2 ; C7.2 58.17,41.73 60.1,43.66 v2(61.04,43.66) ; VR2.2 63.07,23.55 63.09,23.57 73.61,23.57 76.75,20.43 C11.2
  BOTTOM w1.27: C18.2 66.93,41.88 v2(66.93,43.66) 66.9,43.69 R11.2 66.9,47.52 66.88,47.55 67.27,47.94 C13.2 ; C14.2 67.72,43.99
RTN: length 24.2
  TOP w1.27: v1(65.92,66.06) v1(65.92,50.88)
  BOTTOM w1.016: T2.1 98.12,63.78 98.12,67.42
  BOTTOM w1.27: 65.36,69.42 R29.2
SRTN: length 123.1
  BOTTOM w0.305: U3.2 128.63,23.6 130.05,25.02 137.33,25.02 137.67,24.68 137.67,20.9 137.36,20.6
  BOTTOM w0.381: 143.79,20.31 142.89,21.21 140.11,21.21 139.5,20.6 137.64,20.6 ; 127.33,23.6 127.41,23.52 U6.2 ; C38.2 134.26,18.85 133.68,19.43 133.68,19.46 ; Q4.2 R44.2 Q3.2 144.13,6.6 143.81,6.29 143.81,6.23 143.54,5.96 140.69,5.96 J2.1
  BOTTOM w0.508: 122.89,14.83 121.95,13.89 Q5.2 119.96,12.7 119.51,12.24 119.5,10.52 D6.2 ; 122.89,14.83 123.55,14.17 125.45,14.17 126.9,12.73 C9.2 128.35,11.58 128.93,11 128.93,4.88 129.44,4.37 J2.1 139.09,4.37 139.09,6.81 138.53,7.37 138.53,14.91 137.64,15.8 137.64,20.6 U5.2 134.62,20.6 133.68,19.66 R39.2 133.68,19.46 ; 122.89,14.83 C10.2 122.89,16.1 121.36,17.63 R50.1 ; 143.59,18.41 141.25,18.41 140.21,17.37 C36.2 C37.2
  BOTTOM w0.762: D6.2 119.56,6.43 118.06,4.93 114.73,4.93 113.79,5.87 J6.1
VRECT: length 19.8
  BOTTOM w2.032: 34.42,19.61 28.95,14.14 19.4,14.14 C5.1
N11361629: length 47.1
  BOTTOM w2.032: L1.4 9.28,23.96 9.14,23.83 C4.1 9.14,11.99 13.26,7.87 30,7.87 32.03,5.84 BR1.3
N11361637: length 19.9
  BOTTOM w2.032: L2.2 40.51,16.38 37.15,13.02 37.15,2.91 BR1.2
N11361645: length 8.6
  BOTTOM w2.032: F1.1 2.64,74.96 J1.1
N11361649: length 39.9
  BOTTOM w1.27: 9.32,55.91 9.37,55.85 R1.1 9.35,52.35 9.35,49.5 RV1.1
  BOTTOM w2.032: RV1.1 9.32,49.28 9.32,42.11 L1.3 ; C1.1 8.86,68.35 5.03,64.52 F1.2 2.64,59.61 GDT1.1 6.35,55.91 12.88,55.91 C3.1
N11361735: length 18.2
  BOTTOM w2.032: J1.5 24.25,73.72 35.44,73.72 RT1.1
N11361765: length 2.6
  BOTTOM w1.27: R1.2 15.27,52.37
N11361893: length 2.7
  BOTTOM w1.27: 20.62,52.4 R2.1
N11361909: length 43.2
  BOTTOM w1.27: RV1.2 19.66,43.81 26.59,50.75 R2.2 26.59,54.62 C3.2
  BOTTOM w2.032: 26.26,63.09 28.34,61.02 C3.2 ; 26.26,63.09 26.95,63.09 30.73,66.88 C2.2 RT1.2 ; 26.26,63.09 RV2.2 ; RV1.2 19.61,43.76 19.28,43.43 L1.1
N11361917: length 14.2
  BOTTOM w2.032: L1.2 19.28,28.29 C4.2 26.18,21.39 L2.1
N11368602: length 2.5
  BOTTOM w1.27: R4.1 49.59,34.21 R3.2
N11368730: length 3.4
  BOTTOM w0.762: R14.1 66.65,27.46 66.67,27.48 R13.2 66.65,29.46
N11368734: length 2.7
  BOTTOM w0.508: R4.2 R5.1
N11368746: length 9.3
  BOTTOM w0.508: C18.1 69.04,40.06 69.04,40.06 R16.2
  BOTTOM w1.27: C18.1 69.49,41.86 R15.1 71.22,41.76 U2.7
N11368794: length 3.4
  BOTTOM w0.762: U2.6 78.65,42.74 C15.1 80.43,41.14 R12.1
N11368862: length 10.3
  BOTTOM w0.508: R5.2 56.21,23.57 55.17,22.53 Q1.3
N11368870: length 2.5
  BOTTOM w1.27: R8.1 R7.1
N11368874: length 2.5
  BOTTOM w1.27: R8.2 R9.1
N11368882: length 22.3
  TOP w0.508: v2(60.96,45.62) 70.56,45.62 v2(70.84,45.9)
  BOTTOM w0.762: U2.5 75.46,43.87 71.13,43.87 C14.1
  BOTTOM w1.27: C14.1 71,45.74 v2(70.84,45.9) 70.43,46.3 R11.1 ; R9.2 v2(60.96,45.62)
N11368906: length 18.2
  BOTTOM w0.508: R15.2 57.76,38.46 57.76,35.26 63.35,29.67 R14.2
N11368928: length 50.8
  BOTTOM w0.254: C11.1 74.96,20.57 73.15,22.38 64.06,22.38 60.12,18.44 Q2.3
  BOTTOM w0.508: 52.81,22.53 Q1.2 ; 52.81,22.53 50.32,20.04 50.32,17.42 51.38,16.36 54.66,16.36 55.04,16.74 R6.2 Q2.3 57.23,19.88 58.09,20.74 R10.1 ; 52.81,22.53 52.58,22.53 51.87,23.24 51.87,26.59 49.99,28.47 D1.1
N11368966: length 13.4
  BOTTOM w0.508: VR1.1 57.94,25.55 57.58,25.2 57.58,23.24 56.64,22.3 56.64,20.68 56.13,20.17 54.38,20.17 53.9,20.65 Q1.1 52.88,19.61 52.91,19.58 R6.1
N11368994: length 11.8
  TOP w0.508: v2(74.04,39.75) 74.04,40.47 74.07,40.5 74.07,45.03 74.04,45.05 v2(74.04,45.77)
  BOTTOM w0.762: U2.3 74.19,45.62 v2(74.04,45.77) 74.04,46.48 73.25,47.27 C13.1 ; v2(74.04,39.75) 75.56,39.75 U2.9
N11369180: length 4.2
  BOTTOM w0.762: C16.1 84.79,42.72 84.79,41.66 84.25,41.12 R12.2
N11369212: length 4.2
  BOTTOM w0.508: Q2.1 R10.2 VR2.1
N11375827: length 2.6
  BOTTOM w1.27: R26.1 68.7,62.33 D9.1
N11375939: length 2.7
  BOTTOM w1.27: R18.1 R17.1
N11375959: length 27.2
  TOP w0.508: v2(87.73,78.16) v2(87.73,73.86)
  BOTTOM w0.762: C31.1 73.37,77.73 74.95,76.15 81.28,76.15 83.28,78.16 v2(87.73,78.16) ; v2(87.73,73.86) 86.67,72.81 U4.14
  BOTTOM w1.27: R26.2 68.83,77.71 70.48,77.71 70.51,77.73 C31.1
N11375963: length 8.7
  BOTTOM w1.27: R30.1 62.45,71.92 59.85,71.92 ; R29.1 59.86,71.91 59.85,71.92 ; 59.85,71.92 59.56,72.21 C28.2
N11375997: length 9.2
  BOTTOM w0.762: C25.1 82.17,59.57 U4.1 77.84,60.26 R27.2
N11376097: length 45.3
  TOP w1.27: v1(78.08,78.08) v1(78.08,72.64) ; v1(102.07,79.18) v1(102.07,64.86)
  BOTTOM w1.27: v1(78.08,78.08) 80.44,80.44 100.81,80.44 v1(102.07,79.18)
N11376117: length 74.4
  TOP w0.508: v2(90.4,43.71) 90.4,64.03 v2(90.12,64.31)
  TOP w0.762: v2(101.57,19.1) v2(97.46,19.1)
  BOTTOM w0.508: v2(90.12,64.31) 91.74,64.31 C22.1
  BOTTOM w0.762: U7.4 111.34,20.22 110.13,19.01 110.13,18.14 109.22,17.22 102.13,17.22 101.57,17.78 v2(101.57,19.1) ; v2(97.46,19.1) 98.5,20.14 R20.1 98.5,26.16 95.91,28.75 95.91,37.49 92.33,41.07 92.33,41.78 v2(90.4,43.71) ; U4.5 89.93,64.12 v2(90.12,64.31) 90.14,64.29 C22.1
N11376317: length 9.3
  BOTTOM w0.635: C21.1 107.14,26.14 U3.4
  BOTTOM w1.27: C21.1 107.09,28.26 R23.1 107.11,30.44 107.09,30.47 JP3.2
N11376341: length 44.2
  TOP w0.508: v2(87.77,51.69) v2(87.77,59.54)
  BOTTOM w0.508: R28.1 87.9,59.41 v2(87.77,59.54)
  BOTTOM w0.762: R28.1 88.6,59.81 C24.1 88.59,62.19 U4.3 ; v2(87.77,51.69) 88.44,51.69 99.39,40.74 99.39,32.84 101.58,30.65 JP3.1
N11376649: length 4.2
  BOTTOM w1.27: R23.2 104.96,28.26 C21.2 104.95,26.17 R25.1
N11376707: length 8
  BOTTOM w0.762: 88.98,68.27 R22.1 ; 88.98,68.27 88.38,67.67 C23.1 88.24,66.05 U4.7 ; 88.98,68.27 88.98,69.56 R28.2
N11376799: length 9.6
  BOTTOM w0.508: R52.1 108.53,20.07 R21.1
  BOTTOM w0.635: D8.2 107.51,23.6 U3.3
  BOTTOM w0.762: R21.1 107.47,21.74 D8.2
N11376923: length 58.9
  TOP w0.508: v2(78.85,53.29) v2(78.85,64.82)
  BOTTOM w0.762: R25.2 100.71,26.59 97.61,29.69 97.61,39.83 87.78,49.66 82.48,49.66 v2(78.85,53.29) ; U4.6 79.11,65.08 v2(78.85,64.82) C26.1
  BOTTOM w1.27: R25.2 100.71,23.71 R24.2
N11377121: length 114.9
  TOP w0.508: v2(91.8,57.73) v2(91.8,37.87)
  BOTTOM w0.508: C39.2 103.71,20.12 R21.2 ; U4.4 82.85,62.81 85.47,60.2 C25.2 ; 92.35,61.95 92.11,62.19
  BOTTOM w0.762: R20.2 99.8,20.62 99.8,16.94 100.71,16.03 ; 92.91,66.35 93.9,65.36 C22.2 93.9,63.11 92.98,62.19 C24.2 91.9,57.63 v2(91.8,57.73) 91.69,57.63 85.87,57.63 C25.2 ; 92.91,66.35 92.76,66.19 C23.2 ; 92.91,66.35 R22.2 ; 100.71,16.03 100.96,15.77 110.83,15.77 111.79,16.73 U7.3 ; 100.71,16.03 100.43,15.75 98.42,15.75 94.39,19.79 94.39,35.28 v2(91.8,37.87) ; C27.2 R32.1 75.51,66.83 75.51,65.04 C26.2 75.29,63.68 75.82,63.15 U4.4
  BOTTOM w1.27: R20.2 102.16,21.46 102.18,21.44 R21.2
N11377143: length 5
  BOTTOM w0.762: U4.8 80.24,67.02 C27.1 80.12,67.99 R31.1
N11377647: length 7.2
  BOTTOM w0.762: R31.2 74.65,68.94 73.69,67.97 R32.2
  BOTTOM w1.27: R32.2 73.69,66.71 C30.1
N11387015: length 5.3
  BOTTOM w1.27: JP1.2 53.29,41.73 ; 53.29,41.73 53.28,41.72 C6.2 ; 53.29,41.73 C7.1
N11387049: length 12.8
  BOTTOM w0.508: T1.10 54.58,35.5 54.58,30.51 54.03,29.95 54.03,28.45 D3.1 54,26.59 54.03,26.57 D2.2
N11396434: length 70.4
  BOTTOM w0.762: 126.7,6.68 121.79,1.78 78.15,1.78 T1.6 ; 126.7,6.68 D5.2 ; 126.7,6.68 124.92,6.68 123.88,7.72 D6.1
N11396456: length 4.9
  BOTTOM w0.508: JP2.2 C9.1 130.48,13.87 130.51,13.89 C8.2
N11396474: length 76.7
  BOTTOM w0.762: T1.5 66.83,13.63 69.83,13.63 79.98,3.48 120.14,3.48 121.72,5.05 121.72,11.86 122.53,12.67 125.05,12.67 125.97,11.76 125.97,11.35 JP2.1
N11404287: length 32.5
  BOTTOM w0.508: C34.1 159.28,57.12 159.28,41.81 160.6,40.49 VR3.1
N11405404: length 47.8
  BOTTOM w0.508: R40.1 160.58,15.85 162.36,17.63 162.36,42.06 160.76,43.66 160.76,43.97
N11406552: length 13.3
  BOTTOM w0.635: U3.1 R34.1
  BOTTOM w0.762: R34.1 129.24,26.17 D12.1
N11407305: length 8
  BOTTOM w0.508: U5.4 138.95,21.62 139.65,22.32 139.65,22.48 139.67,22.5 R35.1 139.67,25.07 138.58,26.16 D13.2 136.11,26.14
N11407588: length 17.8
  BOTTOM w0.381: R38.2 136.55,8.69 135.31,9.93 135.31,12.01 132.49,14.83 132.49,16.18 131.29,17.37 R36.2 130.51,18.46 130.53,18.48 130.53,20.09 129.82,20.8 U6.3 U6.1
N11410539: length 5.2
  BOTTOM w0.508: U5.1 136.4,19.56 C38.1 136.4,16.41 135.84,15.85 R40.2 134.59,15.85
N11410712: length 5.8
  BOTTOM w0.381: U5.3 R37.2 133.68,21.74 C35.1
N11441238: length 7.7
  BOTTOM w0.381: 149.07,3.43 149.07,5.32 146.84,7.55 R45.2 Q3.1
N11449111: length 5.4
  BOTTOM w1.27: T1.11 48.08,38.19 JP1.1
N11457086: length 1.9
  BOTTOM w0.635: D12.2 131.81,28.12 R33.2
N11457090: length 15.3
  BOTTOM w0.635: VR3.2 151.05,28.12 R33.1
N11461450: length 2.2
  BOTTOM w0.635: D13.1 131.37,26.16 R34.2
N11464509: length 13.6
  BOTTOM w0.381: C37.1 134.45,13.92 133.3,15.07 133.3,16.49 132.26,17.54 R39.1
  BOTTOM w0.508: R37.1 R39.1 ; C37.1 R48.2
N11469796: length 5.7
  BOTTOM w0.381: Q3.3 141.38,7.54 R38.1
  BOTTOM w0.508: R38.1 140.21,8.71 R48.1
N11480149: length 2.7
  BOTTOM w0.508: C35.2 133.76,23.8 R35.2
N11512058: length 6.5
  BOTTOM w2.032: TP4.1 142.8,76.93 J3.1
N11512267: length 7.9
  BOTTOM w2.032: TP5.1 161.14,74.24 J3.4
N11532854: length 6.5
  BOTTOM w0.381: J2.2 R44.1
  BOTTOM w0.508: J2.2 141.63,3.08 141.4,2.84 R43.2 ; R44.1 R46.1
N11552445: length 1.7
  BOTTOM w0.508: R46.2 Q4.1
N11579928: length 2.9
  BOTTOM w0.508: Q5.3 117.78,14.94 U7.2
N11579932: length 7.8
  BOTTOM w0.254: R49.1 116.66,11.94 118.92,14.2 118.92,14.81 119.89,15.77 Q5.1
  BOTTOM w0.508: R50.2 119.94,16.74 119.96,16.71 Q5.1
N11579936: length 5.1
  BOTTOM w0.508: R49.2 115.24,10.03 116.41,8.86 116.41,7.34 J6.2
N11634313: length 2
  BOTTOM w0.508: C39.1 R52.2
N11640064: length 7.1
  BOTTOM w2.032: RV2.1 12.42,62.25 9.9,62.25
N11642887: length 1.5
  BOTTOM w0.508: R51.2 U7.1
N113759751: length 2.8
  BOTTOM w1.27: R19.1 R18.2
N113768551: length 2.1
  BOTTOM w0.762: R24.1 102.81,23.64 D8.1

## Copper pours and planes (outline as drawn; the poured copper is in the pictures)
B+ on BOTTOM: 74.05,30.57 82.65,21.97 88.82,21.97 91.08,24.23 91.69,24.23 91.85,24.08 91.85,19.76 89.48,17.4 82.52,17.4 73.94,25.98 71.04,25.98 69.27,27.76 69.27,30.56 69.28,30.57
B+ on BOTTOM: 63.37,58.6 68.43,53.54 72.09,53.54 72.92,54.38 72.92,55.42 71.91,56.44 70.36,56.44 64.11,62.69 56.54,62.69 54.64,64.59 54.64,71.22 57.76,74.35 83.79,74.35 84.94,75.49 88.47,75.49 90.3,73.66 94.97,73.66 95.71,74.4 92.25,77.85 90.4,77.85 88.95,76.4 84.43,76.4 83.16,75.13 73.38,75.13 72.39,76.12 66.7,76.12 65.18,77.65 54.64,77.65 50.47,73.48 50.47,67.01 48.67,65.2 34.8,65.2 32.72,63.12 32.72,59.33 33.45,58.6
RTN on BOTTOM: 37.16,47.85 61.04,47.85 62.62,46.27 62.62,39.69 65.79,36.53 77.04,36.53 77.83,37.31 79.32,37.31 80.42,36.22 80.42,29.9 81.81,28.5 83.74,28.5 87.68,24.56 89.08,24.56 89.79,25.27 89.79,27.97 83.39,34.37 83.39,38.25 82.12,39.52 77.47,39.52 76.48,38.53 66.5,38.53 65.53,39.5 65.53,48.97 66.95,50.39 66.95,53.24 64.82,55.37 37.62,55.37 29.06,46.81 29.06,45.21 21.48,37.63 4.18,37.63 0.99,34.44 0.99,5.61 6.12,0.48 27.25,0.48 28.57,1.8 28.57,3.38 27.57,4.38 10.17,4.38 5.47,9.08 5.47,32.4 6.99,33.91 23.22,33.91
RTN on BOTTOM: 65.81,70.26 66.67,71.12 80.52,71.12 81.28,70.36 86.03,70.36 88.24,72.57 95.91,72.57 98.58,69.9 98.58,66.42 97.82,66.42 93.12,71.12 88.67,71.12 86.5,68.95 84.7,68.95 84.2,68.45 81.76,68.45 81.75,68.47 81.39,68.47 79.88,69.98 74.07,69.98 72.52,68.43 70,68.43 65.56,63.98 62.28,63.98 60.58,65.68 60.58,68.86 61.98,70.26
SRTN on BOTTOM: 123.67,13.92 121.77,13.92 121.74,13.94 122.58,14.78 123.04,14.78 123.67,14.15
SRTN on BOTTOM: 138.46,7.65 135.74,4.93 129.39,4.93 129.11,5.21 129.11,5.71 128.8,6.02 128.73,5.94 128.73,4.67 129.78,3.62 134.23,3.62 134.24,3.61 139.8,3.61 139.88,3.68 139.88,5.21 140.59,5.92 141.25,5.92 139.95,7.21 139.09,7.21 138.66,7.65
SRTN on BOTTOM: 158.5,40.44 158.95,39.98 158.95,19.15 158.97,19.14 157.99,18.16 141.27,18.16 141.27,18.54 141.4,18.67 141.76,18.67 142.14,19.05 142.14,20.7 141.66,21.18 148.23,21.18 154.89,27.84 154.89,43.92 154.01,44.79 154.03,44.81 154.03,53.21 151,56.24 149.07,56.24 147.96,55.12 147.96,50.04 147.42,49.5 145.95,49.5 145.21,50.24 145.21,51.92 142.29,54.84 142.29,54.91 138.99,54.91 138.38,55.52 138.38,66.32 134.14,70.56 119.02,70.56 118.14,71.45 118.14,78.59 119.33,79.78 125.12,79.78 130.2,74.7 135.86,74.7 142.24,68.33 142.24,65.63 141.48,64.87 141.48,59.44 142.72,58.19 152.86,58.19 154.44,56.6 158.1,56.6 158.5,56.21
VRECT on BOTTOM: 32.74,19.28 32.74,40.26 38.96,46.48 42.75,46.48 43.15,46.08 43.15,40.84 46.63,37.36 46.63,36.22 46.2,35.79 45.11,35.79 44.58,35.26 44.58,25.04 47.57,22.05 47.57,3.61 45.26,1.3 40.77,1.3 40.77,11.2 43.48,13.92 43.48,22.3 41.86,23.93 38.96,23.93 36.55,21.51 36.55,20.37 35.15,18.97 33.05,18.97
N11361765 on BOTTOM (solid shape): 16.38,52.91 15.88,52.91 15.88,49.71 16.38,49.71 16.38,49.1 14.2,49.1 14.2,53.52 16.38,53.52
N11361893 on BOTTOM (solid shape): 21.59,49.12 19.41,49.12 19.41,49.73 19.91,49.73 19.91,52.93 19.41,52.93 19.41,53.54 21.59,53.54
N11361909 on BOTTOM: 29.26,61.24 29.26,65.13 29.41,65.28 28.65,65.28 26.42,63.04 26.42,61.95 27.13,61.24
N11361909 on BOTTOM: 31.45,66.17 31.45,66.22 33.78,68.55 33.45,68.88 31.29,68.88 30.78,68.38 30.78,66.83
N11368632 on BOTTOM: 60.1,37.87 61.65,37.87 65.2,34.32 70.46,34.32 70.89,34.75 74.27,34.75 74.96,34.06 76.2,34.06 77.72,35.59 77.72,36.07 78.38,36.73 78.99,36.73 79.4,36.32 79.4,35.28 77.44,33.32 77.44,31.98 81.76,27.66 83.34,27.66 85.65,25.35 85.65,23.42 85.06,22.83 83.64,22.83 73.99,32.49 63.09,32.49 59.77,35.81 59.77,37.54
N11368928 on BOTTOM: 51.66,23.39 51.66,21.46 51.71,21.41 52.63,22.33 52.63,22.43
N11376097 on BOTTOM: 71.37,73.48 80.75,73.48 81.94,72.29 83.77,72.29 83.77,71.58 83.57,71.37 81.2,71.37 80.8,71.78 71.5,71.78 71.04,72.24 71.04,73.15
N11376097 on BOTTOM: 101.8,69.57 106.45,69.57 110.54,65.48 110.54,57.3 106.73,53.49 101.57,53.49 101.45,53.62 101.45,55.6 101.8,55.96 104.75,55.96 105.49,56.69 105.49,62.28 103.73,64.03 101.45,64.03 100.99,64.49 100.99,68.76
N11394983 on BOTTOM: 70.92,60.73 73.86,60.73 76.2,58.39 78.82,58.39 81.33,55.88 90.7,55.88 90.73,55.85 90.75,55.88 92.71,55.88 93.65,56.82 93.65,60.58 94.89,61.82 96.39,61.82 98.32,59.89 98.32,54.05 101.65,50.72 102.57,50.72 103.53,49.76 103.53,48.21 102.74,47.42 95.63,47.42 89.81,53.24 81.05,53.24 79.48,54.81 75.72,54.81 72.64,57.89 70.89,57.89 70.03,58.75 70.03,59.84
N11395044 on BOTTOM: 128.22,51.21 135.74,51.21 138.25,53.72 141.12,53.72 143.81,51.03 143.81,38.96 141.48,36.63 139.73,36.63 138.94,37.41 138.94,44.58 137.49,46.02 134.09,46.02 134.04,46.08 127.58,46.08 126.92,46.74 126.92,49.91
N11395340 on BOTTOM: 152.96,43.94 153.62,43.28 153.62,36.22 148.59,31.19 140.46,31.19 139.48,32.17 139.48,33.16 140,33.68 145.31,33.68 148.98,37.35 148.98,54.9 149.43,55.35 150.93,55.35 152.96,53.31
N11404287 on BOTTOM: 152.98,59.39 154.84,57.53 158.52,57.53 158.62,57.63 158.62,60.68 157.35,61.95 150.55,61.95 146.81,65.68 144.65,65.68 142.7,63.73 142.7,60.02 143.33,59.39
N11405404 on BOTTOM: 153.57,66.75 158.09,66.75 162.94,61.9 162.94,43.36 162.61,43.03 162.61,40.92 162.59,40.89 162.59,40.92 159.99,43.51 159.99,61.34 158.19,63.14 152.63,63.14 151.99,63.78 151.99,65.18
N11512058 on BOTTOM: 145.11,78.33 150.9,78.33 151.76,77.47 151.76,76.25 149.61,74.09 149.61,72.21 148.51,71.12 144.65,71.12 144.02,71.75 144.02,73 145.11,74.09
N11512267 on BOTTOM: 154.05,78.31 159.41,78.31 159.99,77.72 159.99,75.51 155.45,70.97 152.83,70.97 151.99,71.81 151.99,73.76 153.09,74.85 153.09,77.34
N11634216 on BOTTOM: 145.21,47.85 144.96,47.6 144.96,39.32 141.73,36.09 139.29,36.09 135.15,40.23 129.64,40.23 128.42,39.01 128.42,36.09 129.57,34.95 134.24,34.95 134.29,35 135.36,33.93 139.65,33.93 139.88,34.16 144.86,34.16 147.96,37.26 147.96,47.73 147.83,47.85

Small or netless copper shapes (teardrops, artwork), in the pictures only: 1 on BOTTOM

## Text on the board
Ref Des/Silkscreen Bottom: TM | L | PE | AC INPUT | 100-300VAC | N | CAPZero-2 | HiperPFS-4 | HiperLCS | 2.75A | 39-54VDC | V+ | V-
Ref Des/Silkscreen Top: L | AC INPUT | 100-300VAC | N | JP4 | JP5 | JP6 | JP18 | JP19 | 39-54VDC | 2.75A | JP20 | JP7 | JP9 | JP8 | JP10 | JP11 | JP12 | JP13 | JP14 | JP15 | JP16 | S/N | 1811 | RD-648 | REV G | V+ | V-
User.7: NOTE:  ONE (1) CUTOUT HERE: | PLEASE DELETE THESE PINS | 14.  FAB HOUSE LOGO,DATE CODE TO BE IN SILK SCREEN ONLY.DO NOT USE COPPER. | 13.  MATERIAL FR4 COPPER 2oz THICKNESS 0.062"
User.9: FIGURE | FINISHED_SIZE | 30.0 | 31.0 | 35.0 | 40.0 | 46.0 | 50.0 | 51.0 | 52.0 | 55.0 | 60.0 | 65.0 | 67.0 | 70.0 | 86.0 | 156.0 | DRILL CHART: TOP to BOTTOM | ALL UNITS ARE IN MILS | PLATED | QTY | 2 | 29 | 27 | 26 | 24 | 4 | 6 | 20 | 5 | 9 | 3
